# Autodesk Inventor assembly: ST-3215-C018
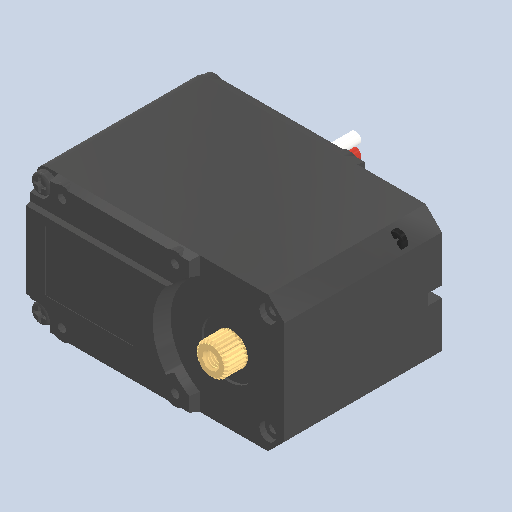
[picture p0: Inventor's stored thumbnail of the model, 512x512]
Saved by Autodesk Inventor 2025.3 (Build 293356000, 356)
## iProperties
Created: 2025-11
Part Number: ST-3215-C018
Document SubType Name: Assembly
Designer: Luis MuÃ±oz
Mass: 49.7219 g
Surface Area: 111.173 cm^2
Volume: 35.5967 cm^3
Density: 1.39681 g/cm^3
Project: TESIS 2 - Plataforma mecatrÃ³nica preventiva desacoplada
Description: Servomotor inteligente FEETECH ST-3215-C018
Vendor: FEETECH
Sending System: Autodesk Translation Framework v14.17.0.0
Preprocessor: ST-DEVELOPER v20.1
Title: Servomotor inteligente FEETECH ST-3215-C018
Revision Number: 00
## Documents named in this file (5)
- C:\Users\Luis M\Desktop\TESIS\CAD_TESIS\FEETECH_ST-3215-C018.iam
- C:\Users\Luis M\Desktop\TESIS\CAD_TESIS\cad\servo-motor_sts3215-v10\servo-motor_sts3215-v10\Composant4.ipt
- C:\Users\Luis M\Desktop\TESIS\CAD_TESIS\cad\servo-motor_sts3215-v10\servo-motor_sts3215-v10\vis.ipt
- C:\Users\Luis M\Desktop\TESIS\CAD_TESIS\cad\servo-motor_sts3215-v10\servo-motor_sts3215-v10\connector F.ipt
- C:\Users\Luis M\Desktop\TESIS\CAD_TESIS\cad\servo-motor_sts3215-v10\servo-motor_sts3215-v10\Pieza69.ipt
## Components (6 placed, 4 different names)
1. Composant4:1 — Coincidencia:2, Nivelación:1
2. vis:1
3. vis:2
4. connector F:1 — Coincidencia:7, Nivelación:2, Nivelación:3
5. connector F:2 — Coincidencia:7, Nivelación:2, Nivelación:3, Coincidencia:8, Coincidencia:9, Coincidencia:10
6. Pieza69 — Coincidencia:2, Nivelación:1, Coincidencia:8, Coincidencia:9, Coincidencia:10
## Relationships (8: Mate 5, Flush 3)
- Coincidencia:2 [Mate]: Composant4:1 ↔ Pieza69
- Nivelación:1 [Flush]: Composant4:1 ↔ Pieza69
- Coincidencia:7 [Mate]: connector F:1 ↔ connector F:2
- Nivelación:2 [Flush]: connector F:1 ↔ connector F:2
- Nivelación:3 [Flush]: connector F:1 ↔ connector F:2
- Coincidencia:8 [Mate]: connector F:2 ↔ Pieza69
- Coincidencia:9 [Mate]: connector F:2 ↔ Pieza69
- Coincidencia:10 [Mate]: connector F:2 ↔ Pieza69
